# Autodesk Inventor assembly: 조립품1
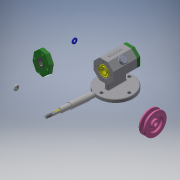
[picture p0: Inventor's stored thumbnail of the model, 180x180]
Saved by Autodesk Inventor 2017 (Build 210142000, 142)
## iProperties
Part Number: 조립품1
Material: 일반
Document SubType Name: Assembly
Designer: mrc
Author: mrc
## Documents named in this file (12)
- C:\Users\mrc\Desktop\조립품1.iam
- C:\Users\mrc\Desktop\본체.ipt
- C:\Users\mrc\Desktop\710204V1026\뒤커버.ipt
- C:\Users\mrc\Desktop\710204V1026\V벨트풀리.ipt
- C:\Users\mrc\Desktop\710204V1026\너트 M8.ipt
- C:\Users\mrc\Desktop\710204V1026\고무캡.ipt
- C:\Users\mrc\Desktop\710204V1026\스프링와셔 8.ipt
- C:\Users\mrc\Desktop\710204V1026\오일 실 15 25 7.ipt
- C:\Users\mrc\Desktop\710204V1026\베어링 15 x 32 x 9.ipt
- C:\Users\mrc\Desktop\710204V1026\축.ipt
- C:\Users\mrc\Desktop\710204V1026\앞커버.ipt
- C:\Users\mrc\Desktop\710204V1026\키 3 x 3 x 12.ipt
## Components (2 placed, 2 different names)
1. V벨트풀리:1
2. 고무캡:1
